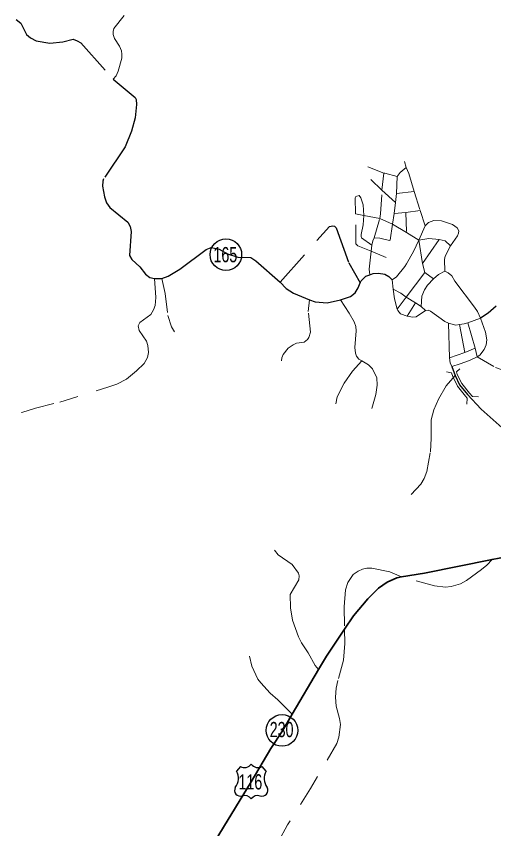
# Model space of a CAD drawing. Extents: x 220.8 to 246.7, y 7287.6 to 7315.8.
# Drawn here: x 230.233 to 232.74, y 7305.147 to 7309.415 of the extents above; entities that cross this region are included whole.
import ezdxf
from ezdxf.enums import TextEntityAlignment as Align

# ---------------------------------------------------------------- set-up
doc = ezdxf.new("R2010")
doc.units = 0
doc.header["$LTSCALE"] = 0.032
for name, pattern in [('DOTTED', [1.5, 0.3, -1.2]), ('LONG_DASHED', [7.5, 6, -1.5]), ('MEDIUM_DASHED', [4.5, 3, -1.5])]:
    doc.linetypes.add(name, pattern=pattern)
for name, color, linetype, lineweight in [('11', 7, 'Continuous', 13), ('12', 7, 'Continuous', 25), ('13', 7, 'Continuous', 25), ('2', 7, 'Continuous', 35), ('4', 7, 'LONG_DASHED', 25), ('6', 7, 'MEDIUM_DASHED', 13), ('7', 7, 'DOTTED', 13), ('8', 7, 'Continuous', 13)]:
    doc.layers.add(name, color=color, linetype=linetype, lineweight=lineweight)
doc.layers.add('61', color=7, linetype='Continuous')

msp = doc.modelspace()

# ---------------------------------------------------------------- linework, layer by layer
at = {"layer": '11'}
for points in [[(232.4919, 7307.5467), (232.5179, 7307.5419), (232.5244, 7307.5229), (232.5498, 7307.4722), (232.5921, 7307.4192), (232.6013, 7307.4093), (232.5994, 7307.3769)], [(232.6601, 7307.416), (232.6289, 7307.4178), (232.6125, 7307.4354), (232.5718, 7307.4864), (232.5483, 7307.533), (232.5439, 7307.5462), (232.5619, 7307.5623)]]:
    msp.add_lwpolyline(points, dxfattribs=at)
at = {"layer": '12'}
for p, q in [((231.4095, 7305.4732), (231.3886, 7305.4489)), ((231.5448, 7305.4491), (231.5238, 7305.4732))]:
    msp.add_line(p, q, dxfattribs=at)
for centre, radius, start, end in [((231.4303, 7305.5133), 0.0452, 242.5287, 323.4161), ((231.5029, 7305.5133), 0.0452, 216.5968, 297.4912), ((231.3254, 7305.4107), 0.0738, 320.9608, 31.1419), ((231.6078, 7305.4107), 0.0738, 148.687, 219.0536), ((231.4106, 7305.3491), 0.0316, 151.5003, 286.5066), ((231.5227, 7305.3491), 0.0316, 253.4942, 28.4996), ((231.4326, 7305.2774), 0.0433, 38.3472, 107.6219), ((231.5006, 7305.2774), 0.0433, 72.467, 141.6528)]:
    msp.add_arc(centre, radius, start, end, dxfattribs=at)
at = {"layer": '13'}
for centre in [(231.3333, 7308.1626), (231.6283, 7305.6631)]:
    msp.add_circle(centre, 0.083, dxfattribs=at)
at = {"layer": '2'}
msp.add_lwpolyline([(231.0941, 7304.7829), (231.4667, 7305.393), (231.5691, 7305.5675), (231.6307, 7305.6606), (231.6815, 7305.7493), (231.8205, 7305.9838), (231.8616, 7306.0529), (231.9562, 7306.1947), (232.0034, 7306.2655), (232.0781, 7306.3547), (232.1346, 7306.4111), (232.1805, 7306.4426), (232.2317, 7306.4649), (232.256, 7306.4694), (232.3773, 7306.4899), (232.7314, 7306.5612), (232.8046, 7306.5753)], dxfattribs=at)
at = {"layer": '4'}
for points in [[(230.2325, 7309.3979), (230.2569, 7309.3783), (230.2863, 7309.3196), (230.3071, 7309.3013), (230.3377, 7309.2854), (230.4098, 7309.2732), (230.4771, 7309.2805), (230.5309, 7309.294), (230.5517, 7309.2866), (230.5725, 7309.2756), (230.7422, 7309.0846), (230.8575, 7308.9882), (230.8624, 7308.9772), (230.8648, 7308.9515), (230.8575, 7308.8805), (230.8379, 7308.812), (230.8049, 7308.7289), (230.6911, 7308.5613), (230.6875, 7308.5491), (230.6862, 7308.5222), (230.696, 7308.4659)], [(230.696, 7308.4659), (230.707, 7308.4353), (230.7242, 7308.4109), (230.8183, 7308.3326), (230.8306, 7308.3106), (230.8355, 7308.2849), (230.8269, 7308.1589), (230.8404, 7308.1369), (230.8807, 7308.0978), (230.9113, 7308.0598), (230.9333, 7308.0427), (230.959, 7308.0366), (230.9969, 7308.0371), (231.0312, 7308.0488), (231.0923, 7308.0867), (231.2305, 7308.1895), (231.2563, 7308.1995), (231.2977, 7308.1917), (231.3425, 7308.1668), (231.3955, 7308.1501), (231.4645, 7308.1471), (231.4911, 7308.1308), (231.6185, 7308.0172)], [(231.6185, 7308.0172), (231.8776, 7308.3106), (231.8947, 7308.3142), (231.9045, 7308.3118), (231.9118, 7308.3032), (231.9791, 7308.1198), (232.0391, 7308.014)], [(232.0391, 7308.014), (232.0439, 7308.0256), (232.0684, 7308.0488), (232.0899, 7308.0572), (232.1063, 7308.0635), (232.1344, 7308.066), (232.1687, 7308.0598), (232.1898, 7308.0474), (232.206, 7308.0305)], [(231.6185, 7308.0172), (231.6501, 7307.984), (231.6892, 7307.9608), (231.7731, 7307.9245), (231.8029, 7307.9143), (231.8653, 7307.9094), (231.9351, 7307.9258), (231.9876, 7307.9436), (232.0121, 7307.962), (232.028, 7307.9877), (232.0391, 7308.014)], [(232.7528, 7307.8919), (232.7115, 7307.8548), (232.6702, 7307.8296)], [(232.5207, 7307.5742), (232.5367, 7307.5271), (232.5608, 7307.4793), (232.6023, 7307.4273), (232.6736, 7307.3508), (232.8007, 7307.2393), (232.8629, 7307.1887), (232.9044, 7307.1498), (232.9329, 7307.1096), (232.9391, 7307.0953)]]:
    msp.add_lwpolyline(points, dxfattribs=at)
at = {"layer": '6'}
for p, q in [((232.2803, 7308.6206), (232.2717, 7308.6525)), ((232.0784, 7308.6232), (232.1621, 7308.5904)), ((232.1532, 7308.5006), (232.1621, 7308.5904)), ((232.2337, 7308.574), (232.2288, 7308.4843)), ((232.0948, 7308.5576), (232.1532, 7308.5006)), ((232.1532, 7308.5006), (232.2243, 7308.4357)), ((232.2288, 7308.4843), (232.2243, 7308.4357)), ((232.2288, 7308.4843), (232.3217, 7308.4951)), ((232.3217, 7308.4951), (232.3537, 7308.3942)), ((232.2243, 7308.4357), (232.2176, 7308.3792)), ((232.0148, 7308.3764), (232.0582, 7308.3686)), ((232.0582, 7308.3686), (232.1412, 7308.3517)), ((232.2176, 7308.3792), (232.2091, 7308.3223)), ((232.2176, 7308.3792), (232.2778, 7308.3841)), ((232.2778, 7308.3841), (232.3537, 7308.3942)), ((232.2778, 7308.3841), (232.2821, 7308.2788)), ((232.3537, 7308.3942), (232.3805, 7308.3134)), ((232.1121, 7308.2512), (232.1412, 7308.3517)), ((232.1412, 7308.3517), (232.2091, 7308.3223)), ((232.2091, 7308.3223), (232.2821, 7308.2788)), ((232.2821, 7308.2788), (232.3459, 7308.2383)), ((232.0962, 7308.1807), (232.1005, 7308.2122)), ((232.1759, 7308.1468), (232.0962, 7308.1807))]:
    msp.add_line(p, q, dxfattribs=at)
for points in [[(230.7998, 7309.4196), (230.7458, 7309.3506), (230.741, 7309.3349), (230.741, 7309.3192), (230.7485, 7309.298), (230.7745, 7309.257), (230.7847, 7309.2337), (230.7875, 7309.216), (230.7875, 7309.1948), (230.767, 7309.1258), (230.7567, 7309.1012), (230.7422, 7309.0846)], [(232.2337, 7308.574), (232.2493, 7308.5939), (232.2803, 7308.6206)], [(232.2803, 7308.6206), (232.295, 7308.5895), (232.3217, 7308.4951)], [(232.1621, 7308.5904), (232.1681, 7308.5913), (232.2337, 7308.574)], [(232.1412, 7308.3517), (232.1457, 7308.3764), (232.1532, 7308.5006)], [(232.0148, 7308.3764), (232.0119, 7308.4609), (232.0156, 7308.4684), (232.0336, 7308.4725), (232.0413, 7308.4609), (232.0551, 7308.4238), (232.0582, 7308.3686)], [(232.0962, 7308.1807), (232.0257, 7308.2089), (232.0154, 7308.2193), (232.0148, 7308.3764)], [(232.0582, 7308.3686), (232.0551, 7308.3185), (232.043, 7308.2685), (232.043, 7308.2581), (232.0456, 7308.2504), (232.1005, 7308.2122)], [(232.2091, 7308.3223), (232.1966, 7308.2391), (232.1932, 7308.2365), (232.1423, 7308.2486), (232.1121, 7308.2512)], [(232.1005, 7308.2122), (232.1043, 7308.2357), (232.1121, 7308.2512)], [(232.0899, 7308.0572), (232.0862, 7308.0872), (232.0962, 7308.1807)], [(232.6535, 7307.625), (232.75, 7307.569), (232.8328, 7307.5407), (232.8818, 7307.5384), (232.9201, 7307.5445), (233.0136, 7307.5821), (233.124, 7307.6365), (233.4259, 7307.8027), (233.4941, 7307.8495), (233.514, 7307.8717), (233.4274, 7307.9591), (233.4067, 7307.9935), (233.3975, 7308.0456), (233.3975, 7308.0932), (233.3906, 7308.1238), (233.373, 7308.1514), (233.336, 7308.1712)], [(230.0737, 7307.2596), (230.2623, 7307.3335), (230.3335, 7307.3566), (230.461, 7307.3885), (230.7133, 7307.4658), (230.7615, 7307.4821), (230.8123, 7307.5092), (230.8646, 7307.5519), (230.9052, 7307.5906), (230.9222, 7307.6225), (230.9263, 7307.6489), (230.9236, 7307.6862), (230.9161, 7307.7079), (230.8774, 7307.7649), (230.872, 7307.7893), (230.8822, 7307.8063), (230.9392, 7307.849), (230.9541, 7307.8734), (230.9615, 7307.8951), (230.9663, 7307.9378), (230.959, 7308.0366)], [(231.6262, 7307.6048), (231.628, 7307.6212), (231.6344, 7307.6376), (231.6608, 7307.6712), (231.6862, 7307.6894), (231.7044, 7307.6976), (231.7445, 7307.7031), (231.7627, 7307.7176), (231.7691, 7307.7277), (231.7772, 7307.7559), (231.7663, 7307.8633), (231.7731, 7307.9245)], [(231.9351, 7307.9258), (231.9811, 7307.856), (232.0066, 7307.8096), (232.0157, 7307.7859), (232.0184, 7307.7622), (232.0102, 7307.674), (232.0139, 7307.6458), (232.0193, 7307.6294), (232.0312, 7307.6139), (232.0465, 7307.605)], [(231.911, 7307.3782), (231.9183, 7307.4164), (231.9547, 7307.4874), (231.9975, 7307.5511), (232.0465, 7307.605)], [(232.0465, 7307.605), (232.083, 7307.5839), (232.104, 7307.5629), (232.1267, 7307.5156), (232.1276, 7307.4774), (232.1213, 7307.4273), (232.0994, 7307.3545)], [(232.7314, 7306.5612), (232.7043, 7306.5321), (232.6762, 7306.5079), (232.5975, 7306.4517), (232.565, 7306.4332), (232.5167, 7306.4186), (232.4869, 7306.4163), (232.4285, 7306.4231), (232.256, 7306.4694), (232.1942, 7306.4956), (232.1004, 7306.5152), (232.074, 7306.5158), (232.051, 7306.5107), (232.0285, 7306.5), (232.0027, 7306.4826), (231.9735, 7306.4399), (231.9622, 7306.4017), (231.9538, 7306.313), (231.9562, 7306.1947), (231.9577, 7306.1201), (231.9519, 7306.0325), (231.9211, 7305.9248), (231.9134, 7305.8854), (231.9096, 7305.8382), (231.9134, 7305.7901), (231.9307, 7305.7267), (231.9346, 7305.694), (231.9259, 7305.6276), (231.9154, 7305.5939), (231.7778, 7305.3582), (231.6576, 7305.1668), (231.4866, 7304.854)]]:
    msp.add_lwpolyline(points, dxfattribs=at)
at = {"layer": '7'}
for points in [[(230.9969, 7308.0371), (231.0151, 7307.958), (231.0288, 7307.8433), (231.0485, 7307.7841), (231.0633, 7307.7578)], [(232.306, 7306.903), (232.3564, 7306.9564), (232.3748, 7306.9873), (232.3891, 7307.0229), (232.408, 7307.1267), (232.4122, 7307.1991), (232.4116, 7307.2953), (232.4251, 7307.3476), (232.4496, 7307.4027), (232.4899, 7307.4727), (232.5367, 7307.5271)], [(231.5884, 7306.6101), (231.6083, 7306.5863), (231.6819, 7306.5346), (231.7156, 7306.4886), (231.7187, 7306.4756), (231.716, 7306.4537), (231.6712, 7306.3774), (231.6731, 7306.3081), (231.6834, 7306.2429), (231.7145, 7306.1544), (231.731, 7306.1226), (231.7658, 7306.0705), (231.8019, 7306.0038), (231.8205, 7305.9838)], [(231.4576, 7306.054), (231.469, 7306.0012), (231.502, 7305.9327), (231.5165, 7305.9128), (231.5657, 7305.8587), (231.6066, 7305.8233), (231.6815, 7305.7493)]]:
    msp.add_lwpolyline(points, dxfattribs=at)
at = {"layer": '8'}
for p, q in [((232.3459, 7308.2383), (232.3655, 7308.1168)), ((232.3655, 7308.1168), (232.4537, 7308.2425)), ((232.3655, 7308.1168), (232.3781, 7308.0692)), ((232.3781, 7308.0692), (232.2805, 7307.9391)), ((232.3781, 7308.0692), (232.4239, 7308.0348)), ((232.2805, 7307.9391), (232.3292, 7307.9098)), ((232.2853, 7307.8395), (232.3292, 7307.9098)), ((232.3292, 7307.9098), (232.3587, 7307.8895)), ((232.3587, 7307.8895), (232.3809, 7307.87)), ((232.5079, 7307.6211), (232.5022, 7307.802)), ((232.6041, 7307.8049), (232.6702, 7307.8296)), ((232.6422, 7307.6707), (232.6041, 7307.8049)), ((232.5602, 7307.7954), (232.5876, 7307.6485)), ((232.5876, 7307.6485), (232.6422, 7307.6707)), ((232.6422, 7307.6707), (232.6535, 7307.625)), ((232.5876, 7307.6485), (232.5079, 7307.6211))]:
    msp.add_line(p, q, dxfattribs=at)
for points in [[(232.3459, 7308.2383), (232.3805, 7308.3134), (232.3981, 7308.3319), (232.4247, 7308.3425), (232.4658, 7308.3399), (232.5229, 7308.3213), (232.5481, 7308.304), (232.5574, 7308.2881), (232.5548, 7308.2748), (232.5495, 7308.2616), (232.5136, 7308.2085)], [(232.3459, 7308.2383), (232.3185, 7308.1793), (232.2813, 7308.1142), (232.2737, 7308.0999), (232.2291, 7308.0454), (232.206, 7308.0305), (232.2125, 7307.9804)], [(232.3459, 7308.2383), (232.3985, 7308.2469), (232.4537, 7308.2425)], [(232.4537, 7308.2425), (232.4843, 7308.2347), (232.5136, 7308.2085)], [(232.5136, 7308.2085), (232.4857, 7308.1554), (232.4818, 7308.1368), (232.4831, 7308.0757)], [(232.4239, 7308.0348), (232.4506, 7308.059), (232.4831, 7308.0757)], [(232.4831, 7308.0757), (232.5003, 7308.0678), (232.5203, 7308.0505), (232.5362, 7308.0226), (232.6397, 7307.8872), (232.6543, 7307.8647), (232.6702, 7307.8296)], [(232.3587, 7307.8895), (232.3628, 7307.9446), (232.376, 7307.9783), (232.3924, 7308.0018), (232.4239, 7308.0348)], [(232.2125, 7307.9804), (232.2189, 7307.931), (232.2335, 7307.8763)], [(232.2125, 7307.9804), (232.2524, 7307.961), (232.2805, 7307.9391), (232.2335, 7307.8763)], [(232.2335, 7307.8763), (232.2362, 7307.8687), (232.2508, 7307.8514), (232.2853, 7307.8395)], [(232.2853, 7307.8395), (232.3158, 7307.8342), (232.3318, 7307.8368), (232.3809, 7307.87)], [(232.3809, 7307.87), (232.3955, 7307.8713), (232.4088, 7307.866), (232.4831, 7307.8116), (232.5022, 7307.802)], [(232.5022, 7307.802), (232.5402, 7307.793), (232.5602, 7307.7954)], [(232.5602, 7307.7954), (232.5853, 7307.7983), (232.6041, 7307.8049)], [(232.6702, 7307.8296), (232.6968, 7307.7558), (232.7034, 7307.7147), (232.6994, 7307.6881), (232.6902, 7307.6642), (232.6676, 7307.635), (232.6535, 7307.625)], [(232.6535, 7307.625), (232.6136, 7307.6065), (232.5636, 7307.5889), (232.5207, 7307.5742), (232.5117, 7307.5945), (232.5079, 7307.6211)]]:
    msp.add_lwpolyline(points, dxfattribs=at)

# ---------------------------------------------------------------- texts
at = {"layer": '61', "width": 0.7}
for s, p in [('165', (231.3306, 7308.1226)), ('230', (231.626, 7305.6279)), ('116', (231.4619, 7305.353))]:
    msp.add_text(s, height=0.08, dxfattribs=at).set_placement(p, align=Align.CENTER)

doc.saveas('drawing.dxf')
